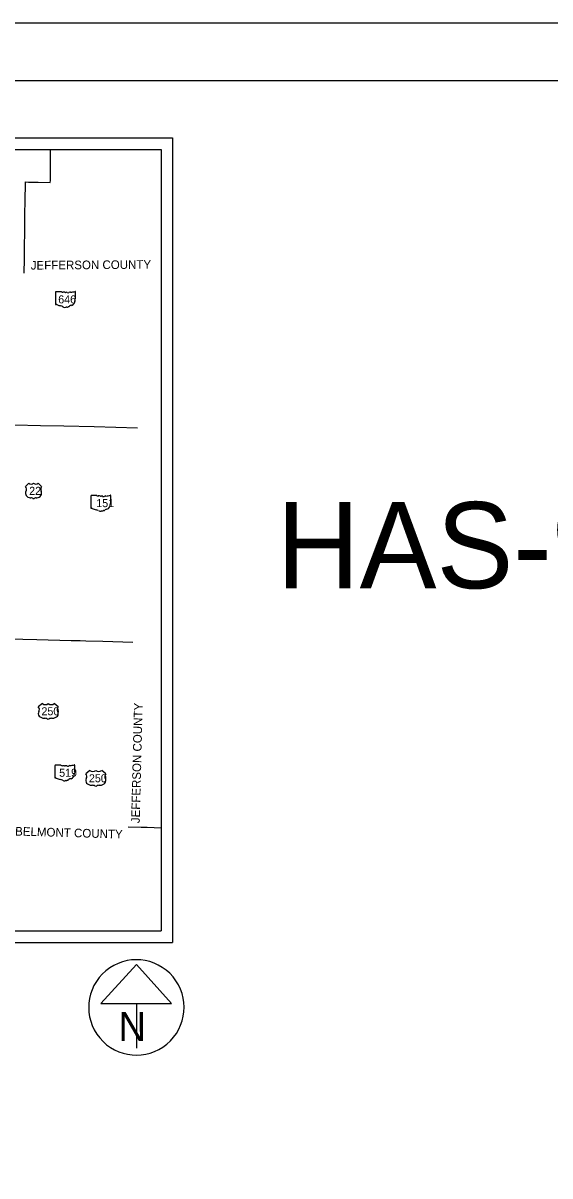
# Model space of a CAD drawing. Extents: x 0 to 70.6, y 0 to 31.9.
# Drawn here: x 7.7 to 12.28, y 11.97 to 22 of the extents above; entities that cross this region are included whole.
import ezdxf

# ---------------------------------------------------------------- set-up
doc = ezdxf.new("R2010")
doc.units = 0
for name, color, linetype in [('GM_X_County', 7, 'Continuous'), ('GM_X_County_Road_Text', 7, 'Continuous'), ('GM_X_County_ROW', 7, 'Continuous'), ('GM_X_Minor_Lake_Text', 7, 'Continuous'), ('GM_X_Minor_River', 7, 'Continuous'), ('GM_X_Minor_River_Text', 7, 'Continuous'), ('GM_X_Section', 7, 'Continuous'), ('GM_X_Township', 7, 'Continuous')]:
    doc.layers.add(name, color=color, linetype=linetype)

msp = doc.modelspace()

# ---------------------------------------------------------------- linework, layer by layer
at = {"layer": 'GM_X_County'}
msp.add_lwpolyline([(1.5, 21.5), (33.5, 21.5), (33.5, 0.5), (1.5, 0.5)], close=True, dxfattribs=at)
at = {"layer": 'GM_X_County_Road_Text'}
for points in [[(7.709, 19.823), (7.709, 19.861), (7.709, 19.873), (7.71, 19.899), (7.711, 20.001), (7.714, 20.239), (7.715, 20.35), (7.717, 20.442), (7.719, 20.618), (7.746, 20.617), (7.763, 20.617), (7.831, 20.616), (7.936, 20.614), (7.937, 20.631), (7.937, 20.644), (7.937, 20.688), (7.937, 20.723), (7.937, 20.736), (7.937, 20.767), (7.939, 20.9)], [(8.615, 15.007), (8.727, 15.004), (8.78, 15.002), (8.9, 14.999)]]:
    msp.add_lwpolyline(points, dxfattribs=at)
at = {"layer": 'GM_X_County_ROW'}
for points in [[(7.321, 16.646), (7.325, 16.786), (7.329, 17.003), (7.331, 17.165), (7.338, 17.444), (7.347, 17.445), (7.347, 17.498), (7.349, 17.607), (7.349, 17.642), (7.352, 17.833), (7.353, 17.89), (7.354, 17.962), (7.357, 18.15), (7.359, 18.296), (7.359, 18.331), (7.362, 18.506), (7.38, 18.506), (7.627, 18.503), (7.852, 18.498), (8.053, 18.495), (8.318, 18.489), (8.694, 18.478)], [(7.289, 15.044), (7.303, 15.476), (7.304, 15.544), (7.305, 15.577), (7.308, 15.577), (7.308, 15.723), (7.309, 15.847), (7.3, 15.847), (7.31, 16.112), (7.314, 16.268), (7.319, 16.517), (7.321, 16.642), (7.321, 16.646), (7.453, 16.644), (7.82, 16.637), (8.117, 16.629), (8.196, 16.627), (8.244, 16.626), (8.392, 16.623), (8.653, 16.613)]]:
    msp.add_lwpolyline(points, dxfattribs=at)
at = {"layer": 'GM_X_Minor_Lake_Text'}
for p, q in [((7.75, 17.997), (7.721, 17.968)), ((7.86, 17.968), (7.831, 17.997)), ((7.761, 17.869), (7.767, 17.869)), ((7.814, 17.869), (7.819, 17.869)), ((7.868, 16.079), (7.831, 16.05)), ((8.005, 16.05), (7.969, 16.079)), ((7.882, 15.951), (7.889, 15.951)), ((7.947, 15.951), (7.955, 15.951)), ((8.281, 15.496), (8.245, 15.467)), ((8.419, 15.467), (8.383, 15.496)), ((8.295, 15.368), (8.303, 15.368)), ((8.361, 15.368), (8.368, 15.368))]:
    msp.add_line(p, q, dxfattribs=at)
for centre, radius, start, end in [((7.688, 17.944), 0.0406, 334.5471, 35.0009), ((7.77, 18.017), 0.029, 225.573, 314.427), ((7.811, 18.017), 0.029, 225.573, 314.427), ((7.893, 17.944), 0.0406, 144.9991, 205.4529), ((7.761, 17.91), 0.0406, 154.8319, 270.6383), ((7.767, 17.84), 0.029, 36.8699, 90), ((7.814, 17.84), 0.029, 90, 143.1301), ((7.82, 17.91), 0.0406, 269.3617, 25.1681)]:
    msp.add_arc(centre, radius, start, end, dxfattribs=at)
for centre, major_axis, start_param, end_param in [((7.893, 16.099), (-0.0363, 0), 0.795399, 2.346194), ((7.944, 16.099), (-0.0363, 0), 0.795399, 2.346194), ((7.882, 15.992), (0.0508, 0), 2.702327, 4.723529), ((7.79, 16.026), (0.0508, 0), 5.838949, 6.894067), ((7.889, 15.922), (-0.0363, 0), 3.785094, 4.712389), ((7.947, 15.922), (-0.0363, 0), 4.712389, 5.639684), ((7.955, 15.992), (-0.0508, 0), 1.559657, 3.580859), ((8.047, 16.026), (-0.0508, 0), 5.672304, 6.727422), ((8.203, 15.444), (0.0508, 0), 5.838949, 6.894067), ((8.306, 15.517), (-0.0363, 0), 0.795399, 2.346194), ((8.357, 15.517), (-0.0363, 0), 0.795399, 2.346194), ((8.46, 15.444), (-0.0508, 0), 5.672304, 6.727422), ((8.295, 15.409), (0.0508, 0), 2.702327, 4.723529), ((8.303, 15.339), (-0.0363, 0), 3.785094, 4.712389), ((8.361, 15.339), (-0.0363, 0), 4.712389, 5.639684), ((8.369, 15.409), (-0.0508, 0), 1.559657, 3.580859)]:
    msp.add_ellipse(centre, major_axis=major_axis, ratio=0.8, start_param=start_param, end_param=end_param, dxfattribs=at)
at = {"layer": 'GM_X_Minor_River_Text'}
for p, q in [((8.155, 19.609), (8.155, 19.664)), ((7.981, 19.659), (7.981, 19.554)), ((8.034, 19.661), (7.983, 19.661)), ((8.155, 19.609), (8.155, 19.609)), ((8.289, 17.886), (8.289, 17.78)), ((8.342, 17.888), (8.291, 17.888)), ((8.463, 17.835), (8.463, 17.89)), ((8.463, 17.835), (8.463, 17.835)), ((7.976, 15.54), (7.976, 15.434)), ((8.029, 15.542), (7.978, 15.542)), ((8.15, 15.489), (8.15, 15.544)), ((8.15, 15.489), (8.15, 15.489))]:
    msp.add_line(p, q, dxfattribs=at)
for centre, major_axis, start_param, end_param in [((8.093, 19.805), (0.185, 0), 4.814394, 5.042369), ((8.153, 19.664), (0.00194, 0), 6.141152, 7.989035), ((7.983, 19.66), (0.00202, 0), 1.712693, 3.28349), ((8.046, 19.674), (0.0196, 0), 4.042523, 4.731795), ((8.052, 19.602), (0.0702, 0), 1.404758, 1.657858), ((8.068, 19.66), (0.00564, 0), 3.836095, 5.185415), ((8.077, 19.648), (0.0117, 0), 0.950623, 2.079405), ((8.092, 19.665), (0.0141, 0), 4.081561, 5.145723), ((8.117, 19.629), (0.0371, 0), 1.699011, 2.107814), ((8.103, 19.578), (0.0462, 0), 5.101752, 6.440018), ((8.162, 19.586), (0.0131, 0), 2.387724, 3.262537), ((8.155, 19.605), (0.003, 0), 1.883978, 3.671073), ((8.136, 19.598), (0.018, 0), 5.934695, 6.695948), ((8.153, 19.608), (0.00207, 0), 5.05454, 6.418171), ((7.983, 19.554), (0.00203, 0), 3.00124, 4.508301), ((7.983, 19.564), (0.0155, 0), 4.665946, 4.897461), ((7.987, 19.548), (0.0056, 0), 0.519207, 1.627899), ((8.057, 19.643), (0.133, 0), 4.195997, 4.488961), ((8.017, 19.506), (0.0417, 0), 0.823519, 1.323587), ((8.063, 19.547), (0.0265, 0), 4.026481, 4.996735), ((8.078, 19.511), (0.0217, 0), 1.495662, 1.94098), ((8.08, 19.539), (0.0141, 0), 4.691044, 5.507374), ((8.093, 19.529), (0.00397, 0), 1.147584, 2.315152), ((8.091, 19.544), (0.0149, 0), 4.937069, 5.64225), ((8.123, 19.524), (0.0253, 0), 1.647645, 2.488434), ((8.291, 17.886), (0.00202, 0), 1.712693, 3.28349), ((8.354, 17.9), (0.0196, 0), 4.042523, 4.731795), ((8.36, 17.829), (0.0702, 0), 1.404758, 1.657858), ((8.376, 17.887), (0.00564, 0), 3.836095, 5.185415), ((8.385, 17.875), (0.0117, 0), 0.950623, 2.079405), ((8.4, 17.891), (0.0141, 0), 4.081561, 5.145723), ((8.425, 17.856), (0.0371, 0), 1.699011, 2.107814), ((8.401, 18.032), (0.185, 0), 4.814394, 5.042369), ((8.461, 17.891), (0.00194, 0), 6.141152, 7.989035), ((8.291, 17.78), (0.00203, 0), 3.00124, 4.508301), ((8.291, 17.791), (0.0155, 0), 4.665946, 4.897461), ((8.295, 17.774), (0.0056, 0), 0.519207, 1.627899), ((8.365, 17.869), (0.133, 0), 4.195997, 4.488961), ((8.325, 17.733), (0.0417, 0), 0.823519, 1.323587), ((8.371, 17.774), (0.0265, 0), 4.026481, 4.996735), ((8.388, 17.766), (0.0141, 0), 4.691044, 5.507374), ((8.401, 17.756), (0.00397, 0), 1.147584, 2.315152), ((8.399, 17.77), (0.0149, 0), 4.937069, 5.64225), ((8.431, 17.751), (0.0253, 0), 1.647645, 2.488434), ((8.411, 17.805), (0.0462, 0), 5.101752, 6.440018), ((8.47, 17.812), (0.0131, 0), 2.387724, 3.262537), ((8.463, 17.831), (0.003, 0), 1.883978, 3.671073), ((8.444, 17.824), (0.018, 0), 5.934695, 6.695948), ((8.461, 17.835), (0.00207, 0), 5.05454, 6.418171), ((8.386, 17.737), (0.0217, 0), 1.495662, 1.94098), ((7.978, 15.54), (0.00202, 0), 1.712693, 3.28349), ((8.041, 15.554), (0.0196, 0), 4.042523, 4.731795), ((8.048, 15.482), (0.0702, 0), 1.404758, 1.657858), ((8.063, 15.541), (0.00564, 0), 3.836095, 5.185415), ((8.072, 15.529), (0.0117, 0), 0.950623, 2.079405), ((8.087, 15.545), (0.0141, 0), 4.081561, 5.145723), ((8.112, 15.51), (0.0371, 0), 1.699011, 2.107814), ((8.088, 15.686), (0.185, 0), 4.814394, 5.042369), ((8.099, 15.459), (0.0462, 0), 5.101752, 6.440018), ((8.157, 15.466), (0.0131, 0), 2.387724, 3.262537), ((8.15, 15.485), (0.003, 0), 1.883978, 3.671073), ((8.131, 15.478), (0.018, 0), 5.934695, 6.695948), ((8.148, 15.545), (0.00194, 0), 6.141152, 7.989035), ((8.148, 15.489), (0.00207, 0), 5.05454, 6.418171), ((7.978, 15.434), (0.00203, 0), 3.00124, 4.508301), ((7.979, 15.445), (0.0155, 0), 4.665946, 4.897461), ((7.982, 15.428), (0.0056, 0), 0.519207, 1.627899), ((8.052, 15.523), (0.133, 0), 4.195997, 4.488961), ((8.013, 15.387), (0.0417, 0), 0.823519, 1.323587), ((8.058, 15.428), (0.0265, 0), 4.026481, 4.996735), ((8.073, 15.391), (0.0217, 0), 1.495662, 1.94098), ((8.075, 15.42), (0.0141, 0), 4.691044, 5.507374), ((8.088, 15.41), (0.00397, 0), 1.147584, 2.315152), ((8.086, 15.424), (0.0149, 0), 4.937069, 5.64225), ((8.118, 15.405), (0.0253, 0), 1.647645, 2.488434)]:
    msp.add_ellipse(centre, major_axis=major_axis, ratio=0.8, start_param=start_param, end_param=end_param, dxfattribs=at)
at = {"layer": 'GM_X_Section'}
msp.add_lwpolyline([(0, 0), (34, 0), (34, 22), (0, 22)], close=True, dxfattribs=at)
at = {"layer": 'GM_X_Township'}
for p, q in [((2, 21), (9, 21)), ((9, 21), (9, 14)), ((2.1, 20.9), (8.9, 20.9)), ((8.9, 20.9), (8.9, 14.1)), ((2.1, 14.1), (8.9, 14.1)), ((2, 14), (9, 14)), ((8.685, 13.809), (8.377, 13.468)), ((8.992, 13.468), (8.685, 13.809)), ((8.377, 13.468), (8.992, 13.468)), ((8.685, 13.468), (8.685, 13.081)), ((8.685, 13.435), (8.685, 13.435)), ((8.685, 13.435), (8.685, 13.435))]:
    msp.add_line(p, q, dxfattribs=at)
msp.add_arc((8.685, 13.435), 0.415, 129.7798, 129.7633, dxfattribs=at)

# ---------------------------------------------------------------- texts
at = {"layer": 'GM_X_Minor_Lake_Text'}
for s, p in [('22', (7.752, 17.895)), ('250', (7.859, 15.977)), ('250', (8.272, 15.394))]:
    msp.add_text(s, height=0.0696, dxfattribs=at).set_placement(p)
at = {"layer": 'GM_X_Minor_River'}
for s, rotation, p in [('JEFFERSON COUNTY', 0.4072, (7.766, 19.855)), ('JEFFERSON COUNTY', 88.5722, (8.714, 15.037)), ('BELMONT COUNTY', 358.3527, (7.629, 14.931))]:
    msp.add_text(s, height=0.075, rotation=rotation, dxfattribs=at).set_placement(p)
at = {"layer": 'GM_X_Minor_River_Text'}
for s, p in [('646', (8.005, 19.561)), ('151', (8.336, 17.788)), ('519', (8.013, 15.442))]:
    msp.add_text(s, height=0.0696, dxfattribs=at).set_placement(p)
at = {"layer": 'GM_X_Township'}
for s, height, p in [('HAS-9-VAR, HAS-646-1.15', 0.75, (9.904, 17.082)), ('N', 0.25, (8.529, 13.144))]:
    msp.add_text(s, height=height, dxfattribs=at).set_placement(p)

doc.saveas('drawing.dxf')
